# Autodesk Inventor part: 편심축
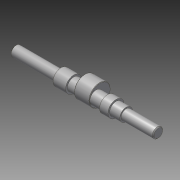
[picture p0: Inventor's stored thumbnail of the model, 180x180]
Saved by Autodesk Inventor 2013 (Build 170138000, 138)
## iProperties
Company: 한국ATC센터
Created: 2014-02
Part Number: 편심축
Document SubType Name: Modeling
Designer: KYOUNG IL JANG
Density: 7.86 g/cm^3
Mass: 251.16 g
Surface Area: 94.6886 cm^2
Volume: 31.9542 cm^3
Material: 강, 연강
Vendor: CBT Solutions
Author: KYOUNG IL JANG
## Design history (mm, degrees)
sketch "스케치1"
  geometry: L1 (-84.5, 0)-(84.5, 0); L2 (-84.5, 0)-(-84.5, 6); L3 (-84.5, 6)-(-30.5, 6); L4 (-30.5, 6)-(-30.5, 9.5); L5 (-30.5, 9.5)-(-15.5, 9.5); L6 (-15.5, 9.5)-(-15.5, 7.5); L7 (-15.5, 7.5)-(46.5, 7.5); L8 (84.5, 6)-(84.5, 0); L9 (34.5, 7.5)-(34.5, 9.5); L10 (34.5, 9.5)-(24.5, 9.5); L11 (24.5, 9.5)-(24.5, 7.5); L12 (46.5, 7.5)-(46.5, 6); L13 (46.5, 6)-(84.5, 6); 2 further points
  constraints: 26 end point, 6 parallel, 6 perpendicular, 2 point on line, 1 coincident, 1 horizontal, 1 midpoint
  dimensions: "d1" = 12 diameter of L3 L1; "d2" = 15 diameter of L7 L1; "d4" = 15 distance of L4.end L5.end; "d5" = 19 diameter of L5 L1; "d24" = 10 distance of L9.end L10.end; "d25" = 19 diameter of L10 L1; "d27" = 40 distance between parallel lines of L11 L6; "d28" = 54 distance of L2.end L3.end; "d29" = 50 distance between parallel lines of L8 L9; "d41" = 38 distance between parallel lines of L8 L12; "d42" = 12 diameter of L13 L1
revolve "회전1" stored, may be unused: angle "d6" = 90 deg
node "작업 평면1"
sketch "스케치2"
  geometry: C1 r 7.5 at (0, 0) reference; C2 r 12.5 at (0, 4.5); 1 further point
  constraints: 1 centre point, 1 vertical alignment
  dimensions: "d8" = 4.5 distance of point (0, 0) C2.centre; "d9" = 25 diameter of C2
extrude "돌출1" join sketch "스케치2" distance "d10" = 18; taper "d11" = 0 deg
chamfer "모따기1" distance "d12" = 1; stored, may be unused: second distance "d13" = 2, angle "d14" = 45 deg
chamfer "모따기2" distance "d15" = 0.5; stored, may be unused: second distance "d16" = 2, angle "d17" = 45 deg
node "작업 평면2"
sketch "스케치3"
  geometry: L1 (4, -2)-(18, -2); L2 (18, 2)-(4, 2); L3 (27, 5)-(27, -5) reference; L4 (-137, -2)-(-123, -2); L5 (-123, 2)-(-137, 2); L6 (-142, -5)-(-142, 5) reference; A1 r 2 centre (18, 0) between (18, -2) and (18, 2); A2 r 2 centre (4, 0) between (4, 2) and (4, -2); A3 r 2 centre (-123, 0) between (-123, -2) and (-123, 2); A4 r 2 centre (-137, 0) between (-137, 2) and (-137, -2); 2 further points
  constraints: 8 end point, 8 point on circle, 8 tangent, 4 centre point, 2 horizontal, 2 horizontal alignment, 2 parallel, 1 midpoint
  dimensions: "d18" = 7 distance edge to line of A1 L3; "d19" = 4 distance between parallel lines of L2 L1; "d20" = 18 dimension on A1 A2; "d43" = 4 distance between parallel lines of L5 L4; "d44" = 18 dimension on A3 A4; "d45" = 3 distance edge to line of A4 L6
extrude "돌출2" cut sketch "스케치3" distance "d21" = 2.5; taper "d22" = 0 deg
revolve "회전2" stored, may be unused: angle "d26" = 90 deg
node "솔리드1"
other parameters: "d7" = 8.5
